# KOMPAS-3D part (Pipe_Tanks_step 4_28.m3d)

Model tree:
1. X Axis
2. Y Axis
3. Z Axis  (labels: Valve Dy 50; Pipe Dn 20)
     Òîëùèíà ñòåíêè 1 = 1

Referenced files in C:\Documents and Settings\kashirsky\Мои документы\Camtasia Studio\Pipelines3D\Tanks\: Tanks_step 4.a3d
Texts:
  Pipe Dn 20
  Steel ASTM A295
  Three Point Plane
  Plane at Angle
  Line and Point Plane
  Axis through Two Vertices
  Axis of Feature
  Axis of Conical Surface
  Axis through Edge
  Trim by Surface
  Trim by Sketch
  Feature with No History
  Intersection Axis of Two Planes
  Two Line Plane
  Line and Face Plane
  Bend by line
  Hole in sheet body
  Cut in sheet body
  Point in CM
  Linear Dimension from Line to Point
  Surface Finish Symbol
  Geometric Tolerance Symbol
  Leader #1
  Leader #2
  Leader #3
  Shape Deviations and Datum
  Node point number
  Mark of coordination axis
  Node point designation
  Mark/Reference designation with leader
  Mark/reference designation on line
  Mark/Reference designation without leader
  Valve Dy 50
  Plane of section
